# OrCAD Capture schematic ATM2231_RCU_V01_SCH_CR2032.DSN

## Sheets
1 1.TITLE: title: ATM2231_REMOTE_CONTROL_REF_DESIGN; rev: 01
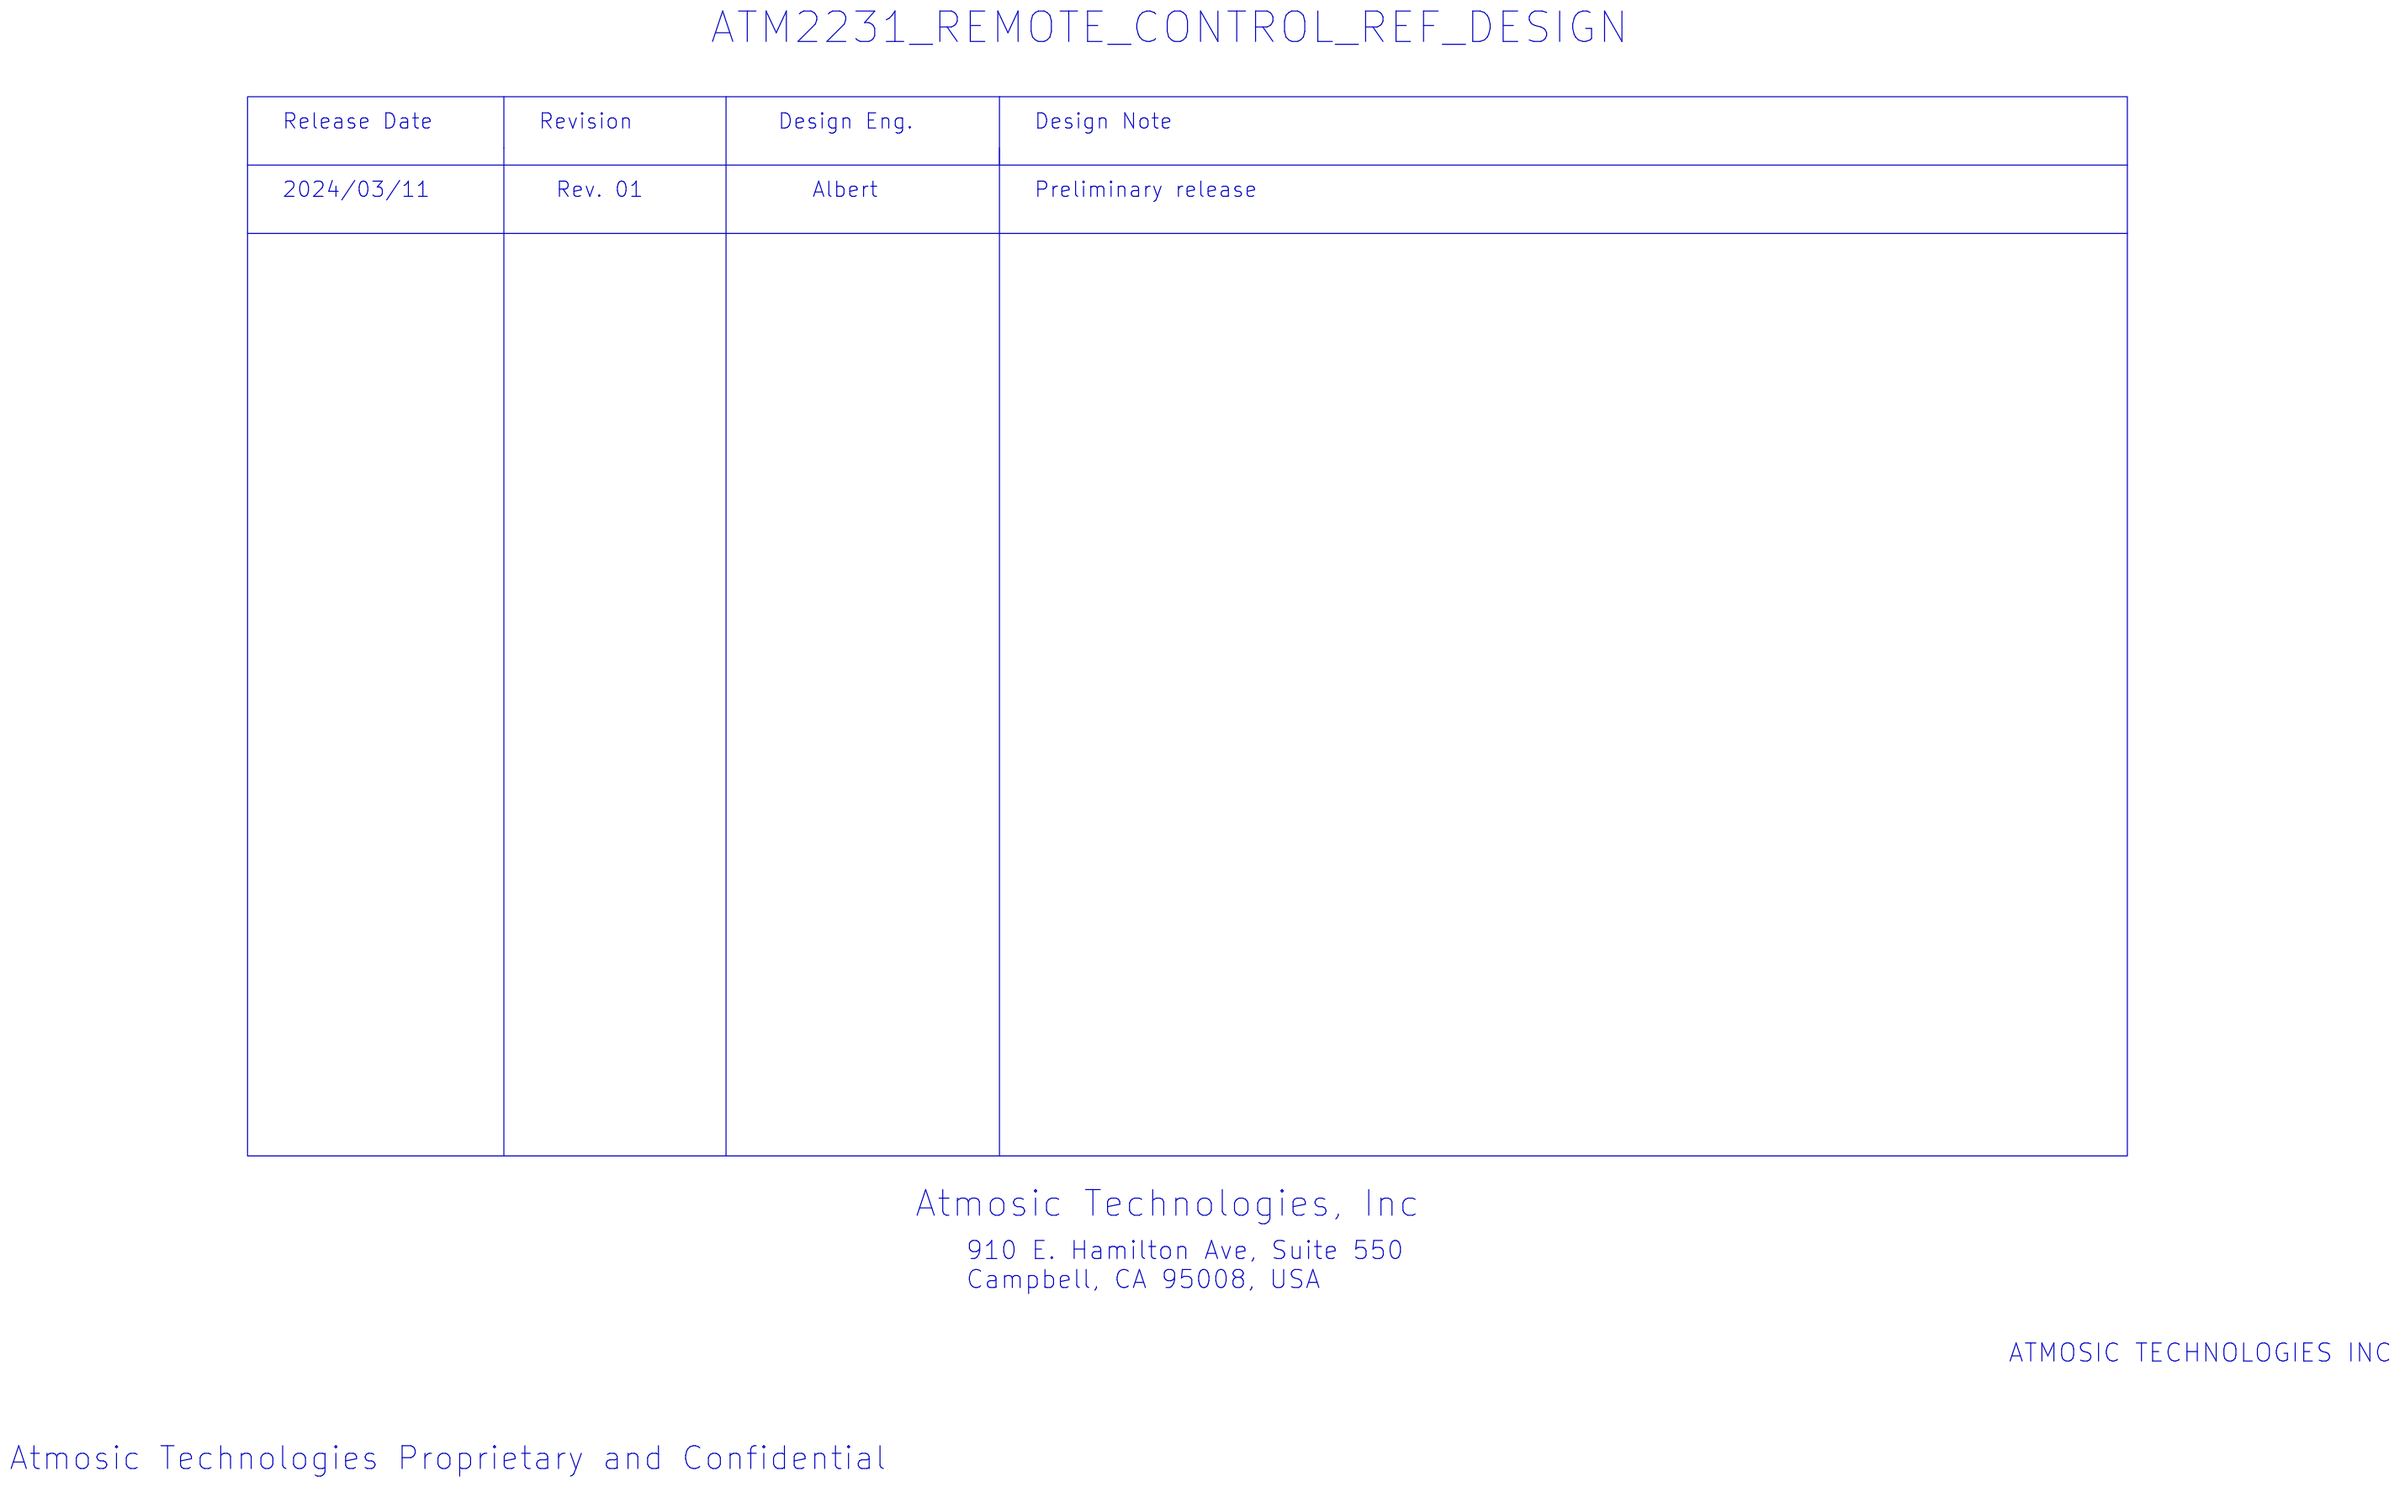
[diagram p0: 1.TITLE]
2 2.BLOCK DIAGRAM
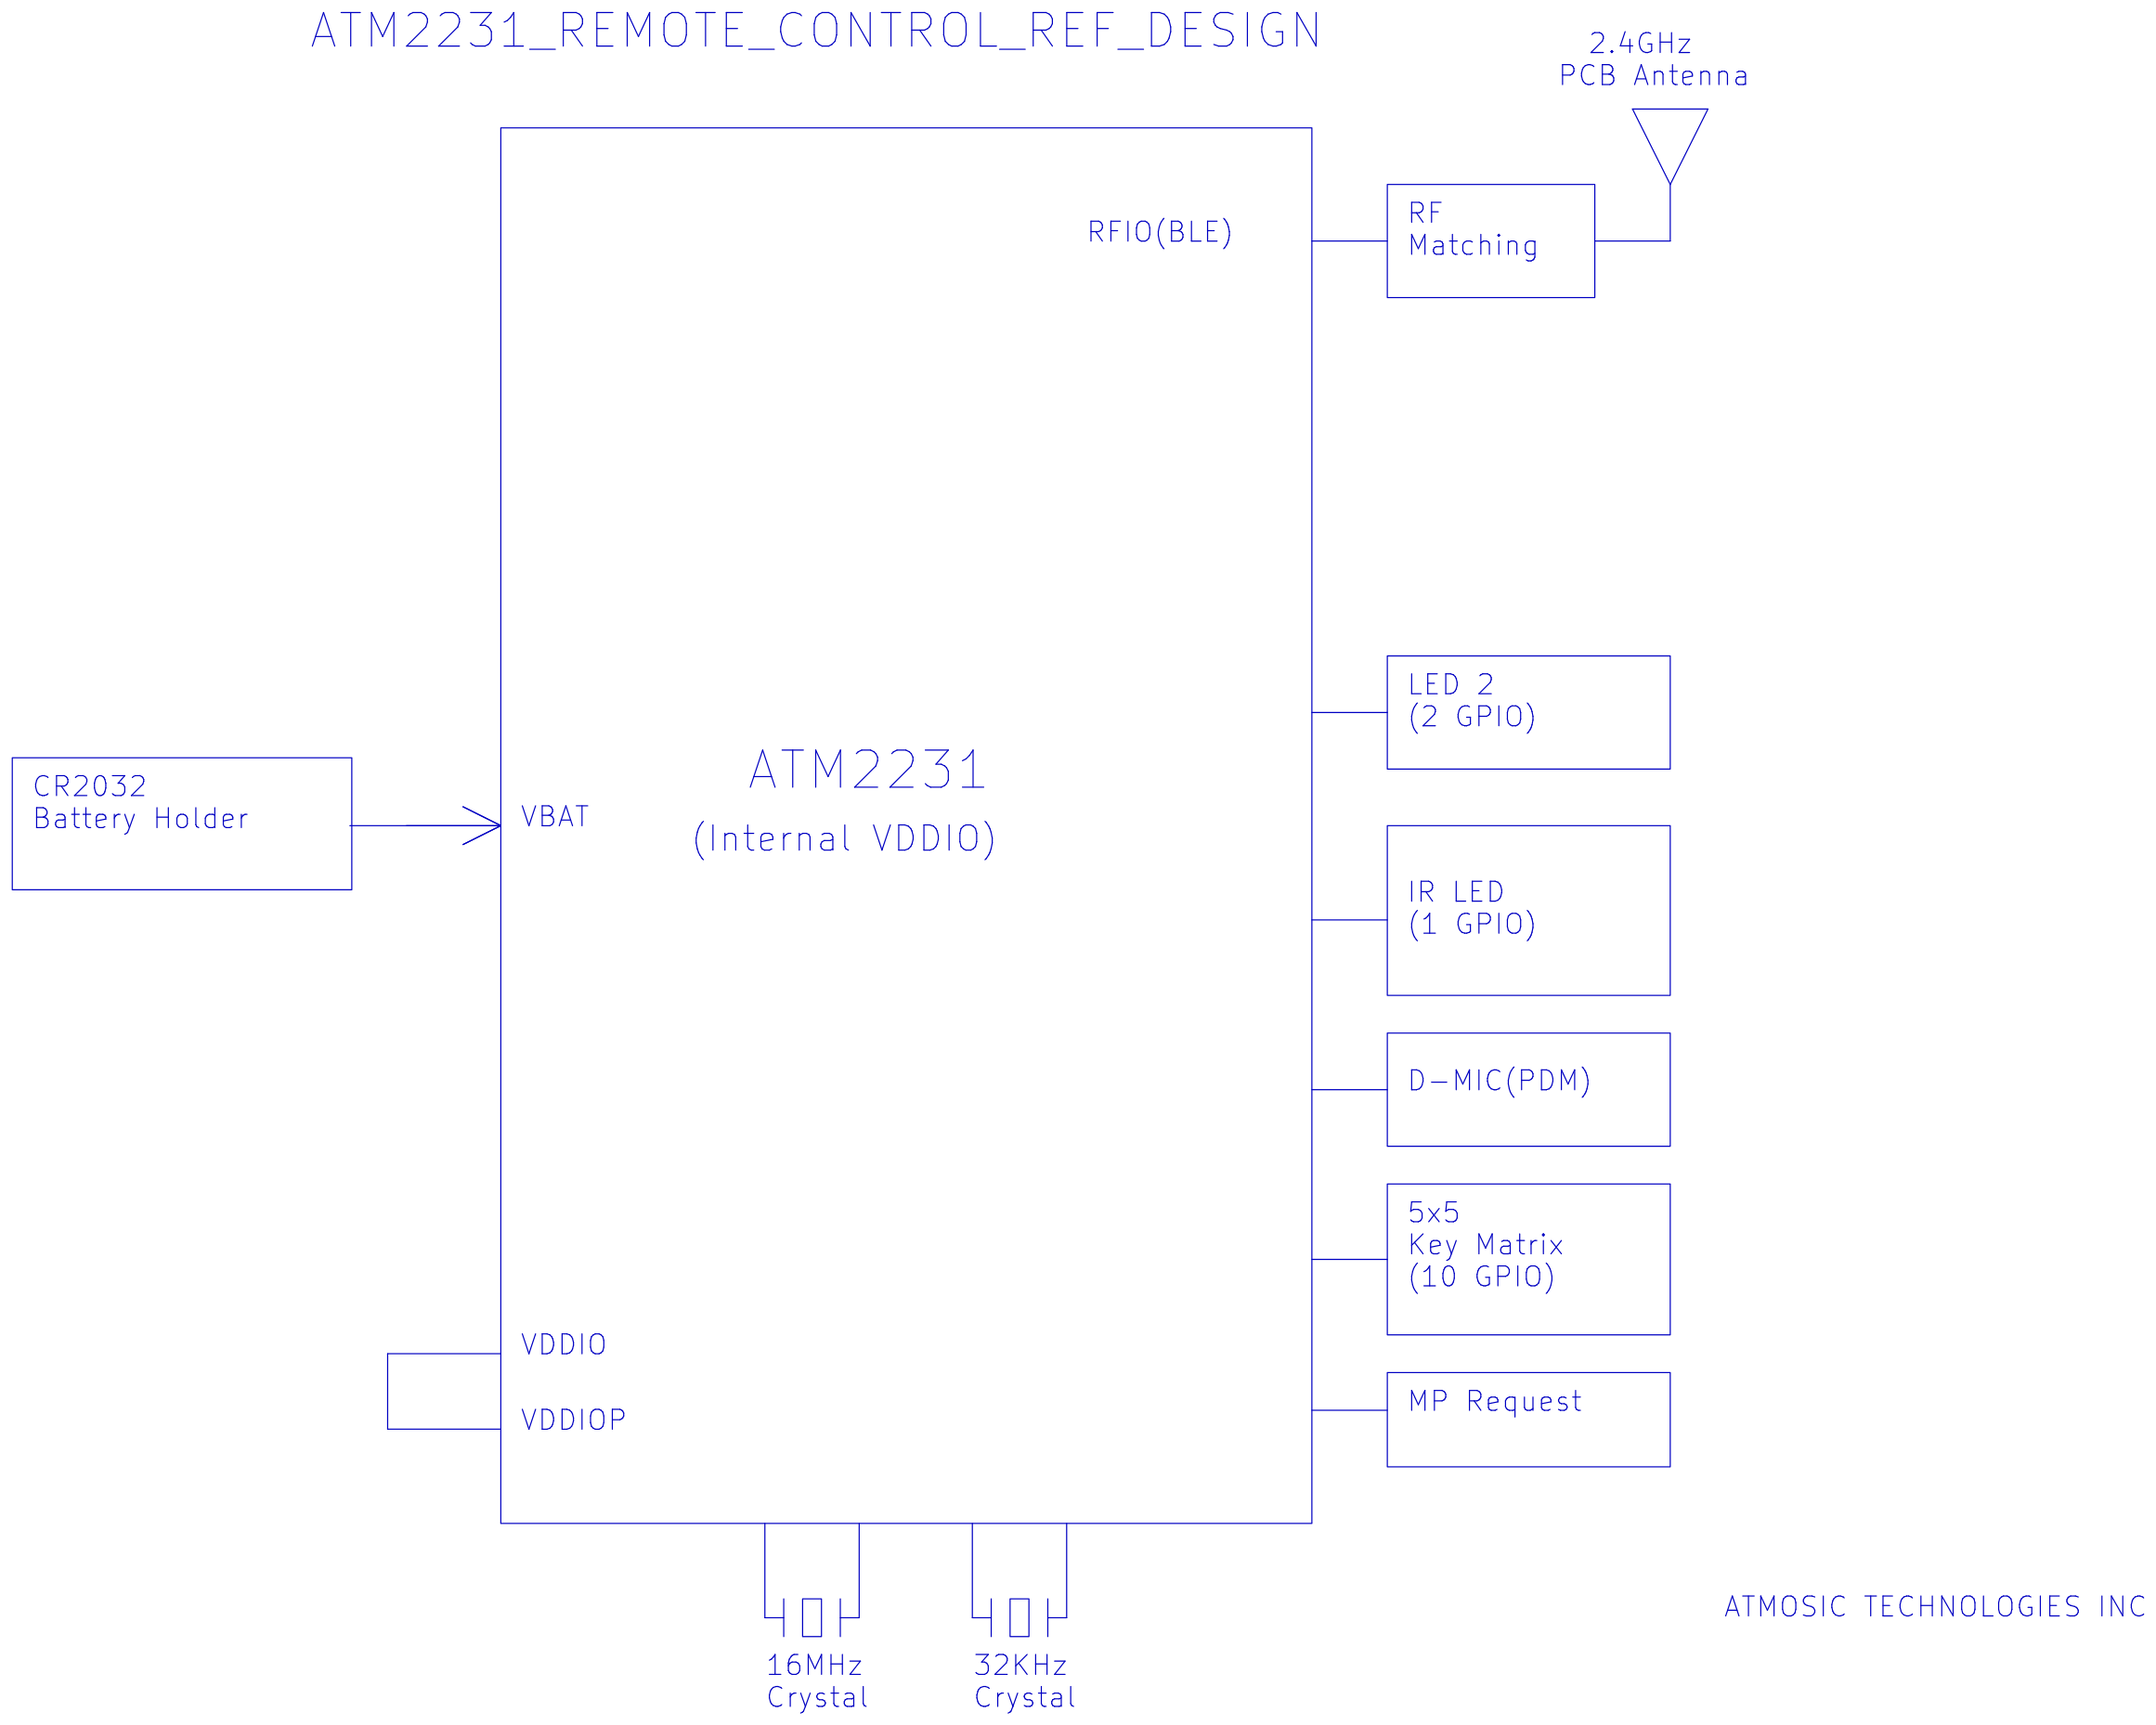
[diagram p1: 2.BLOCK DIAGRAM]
3 3.ATM2231: size C
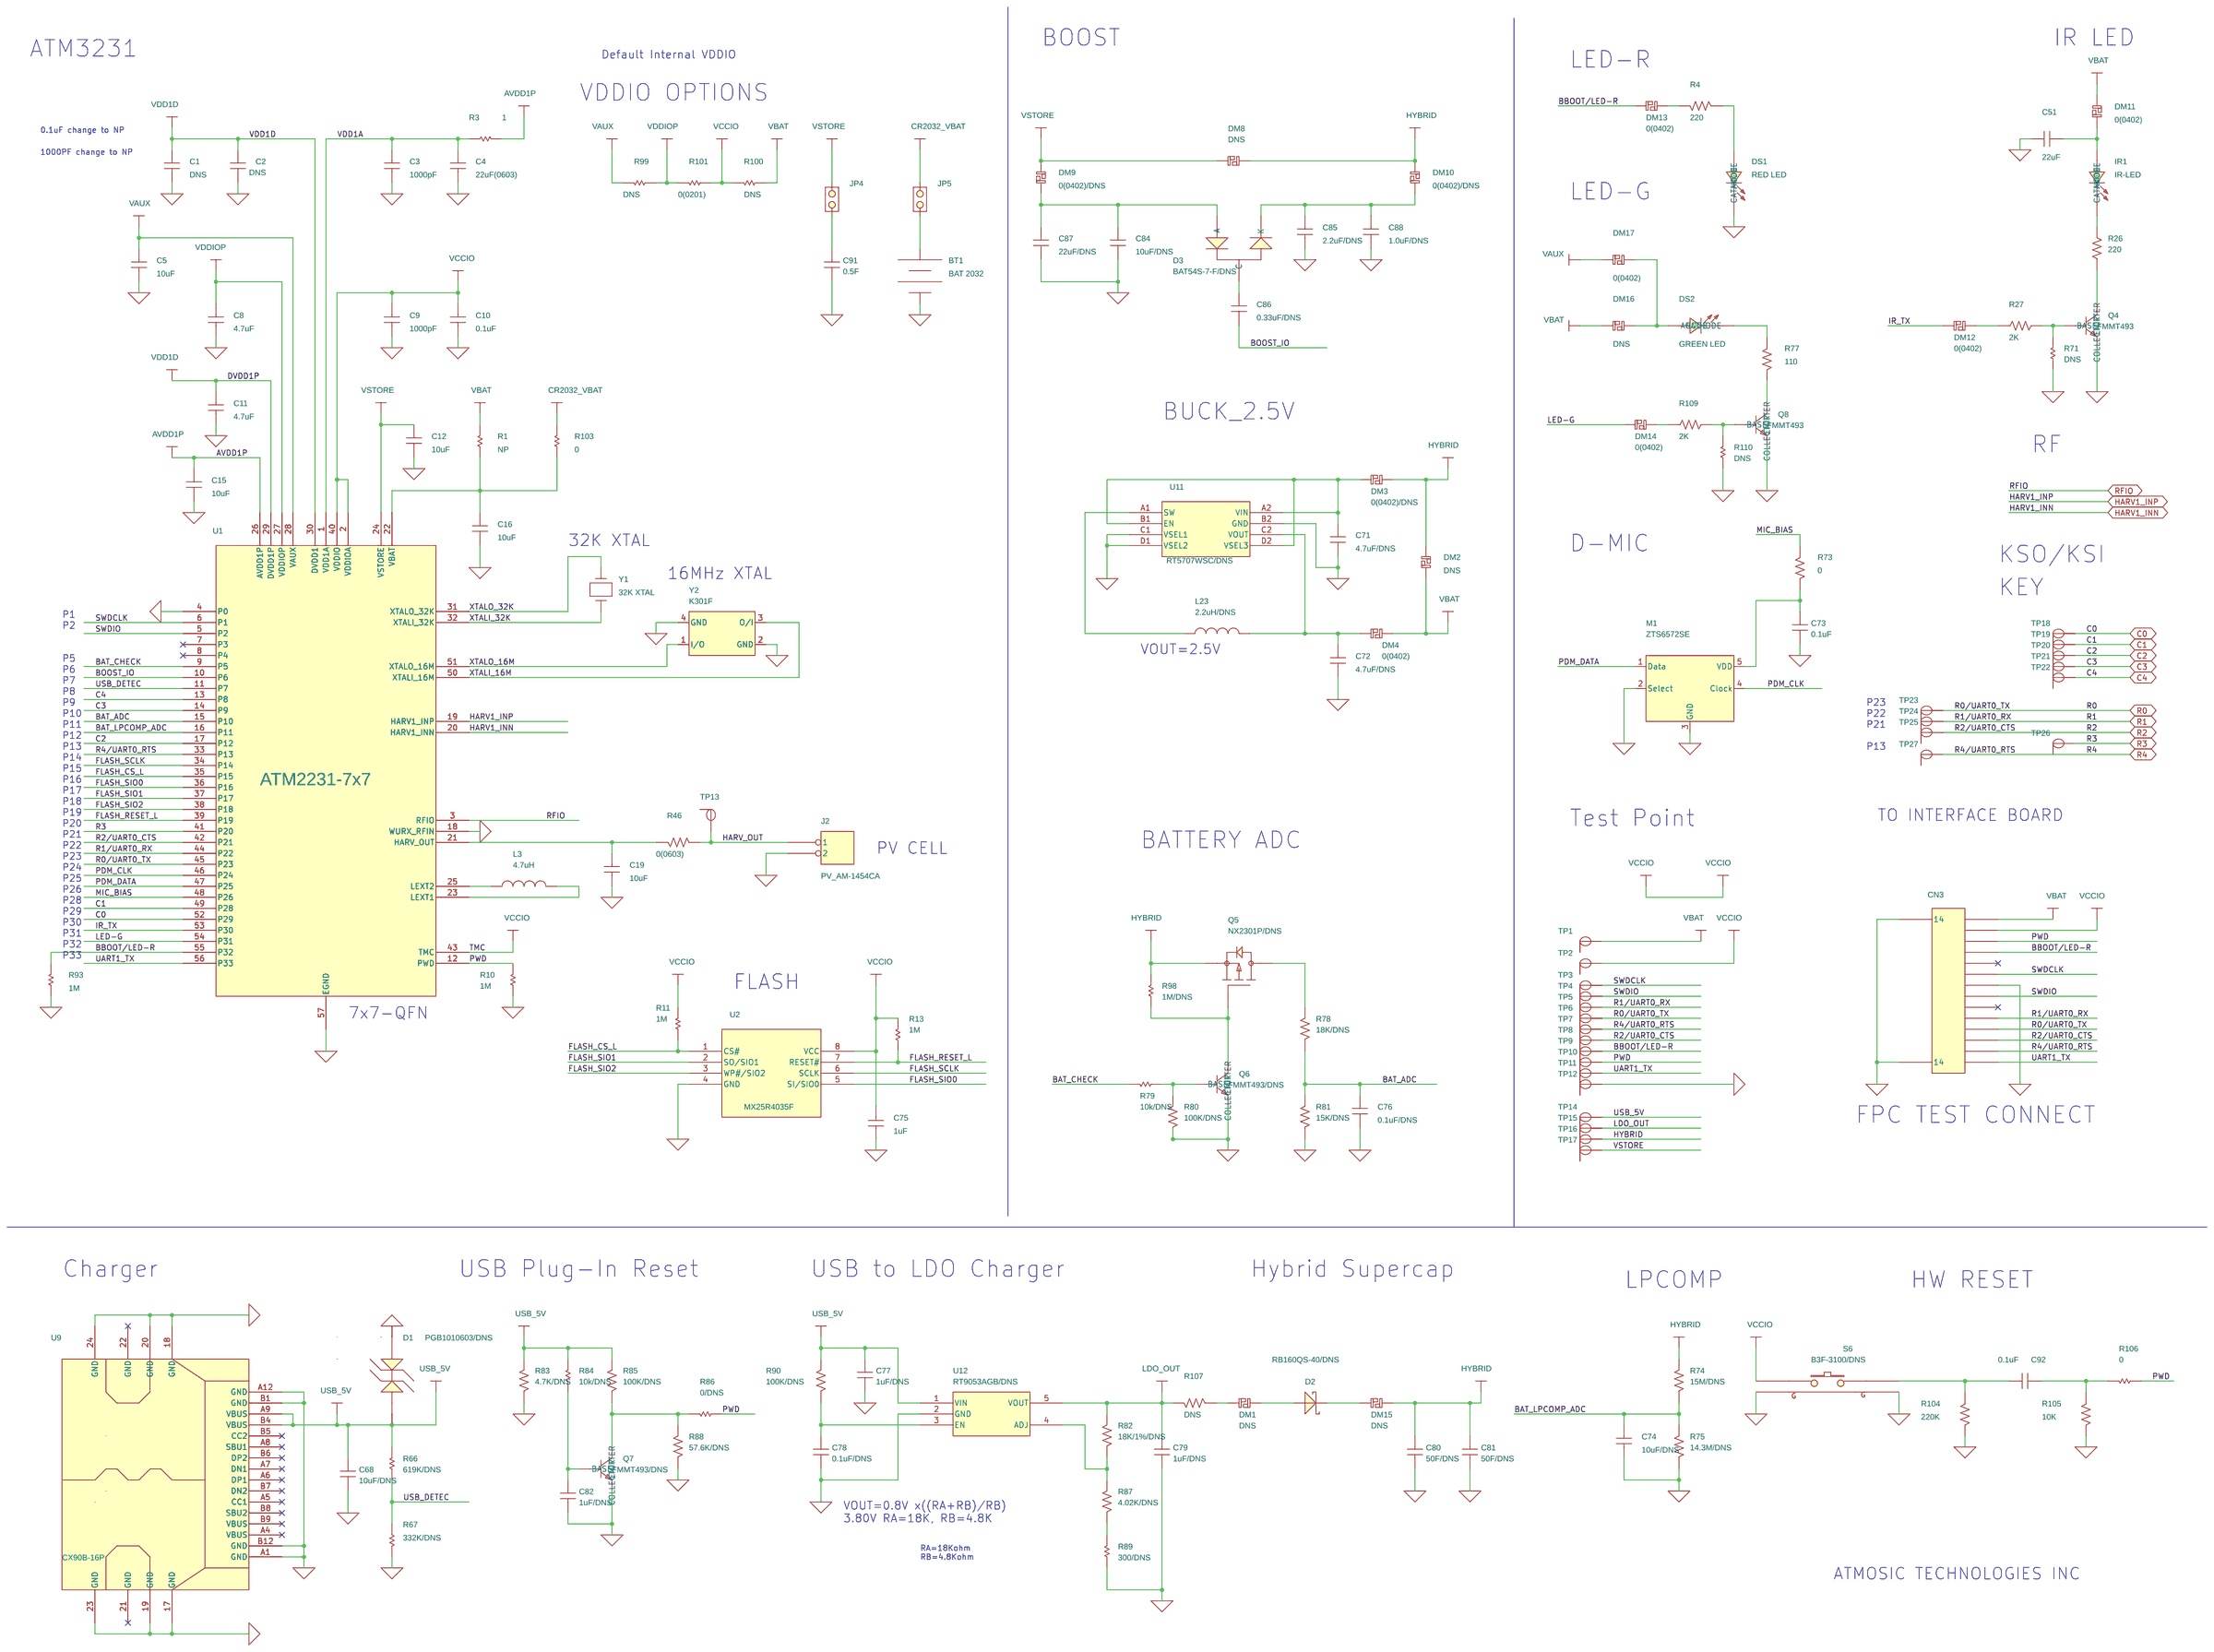
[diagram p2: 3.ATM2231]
4 4.KEY: size B
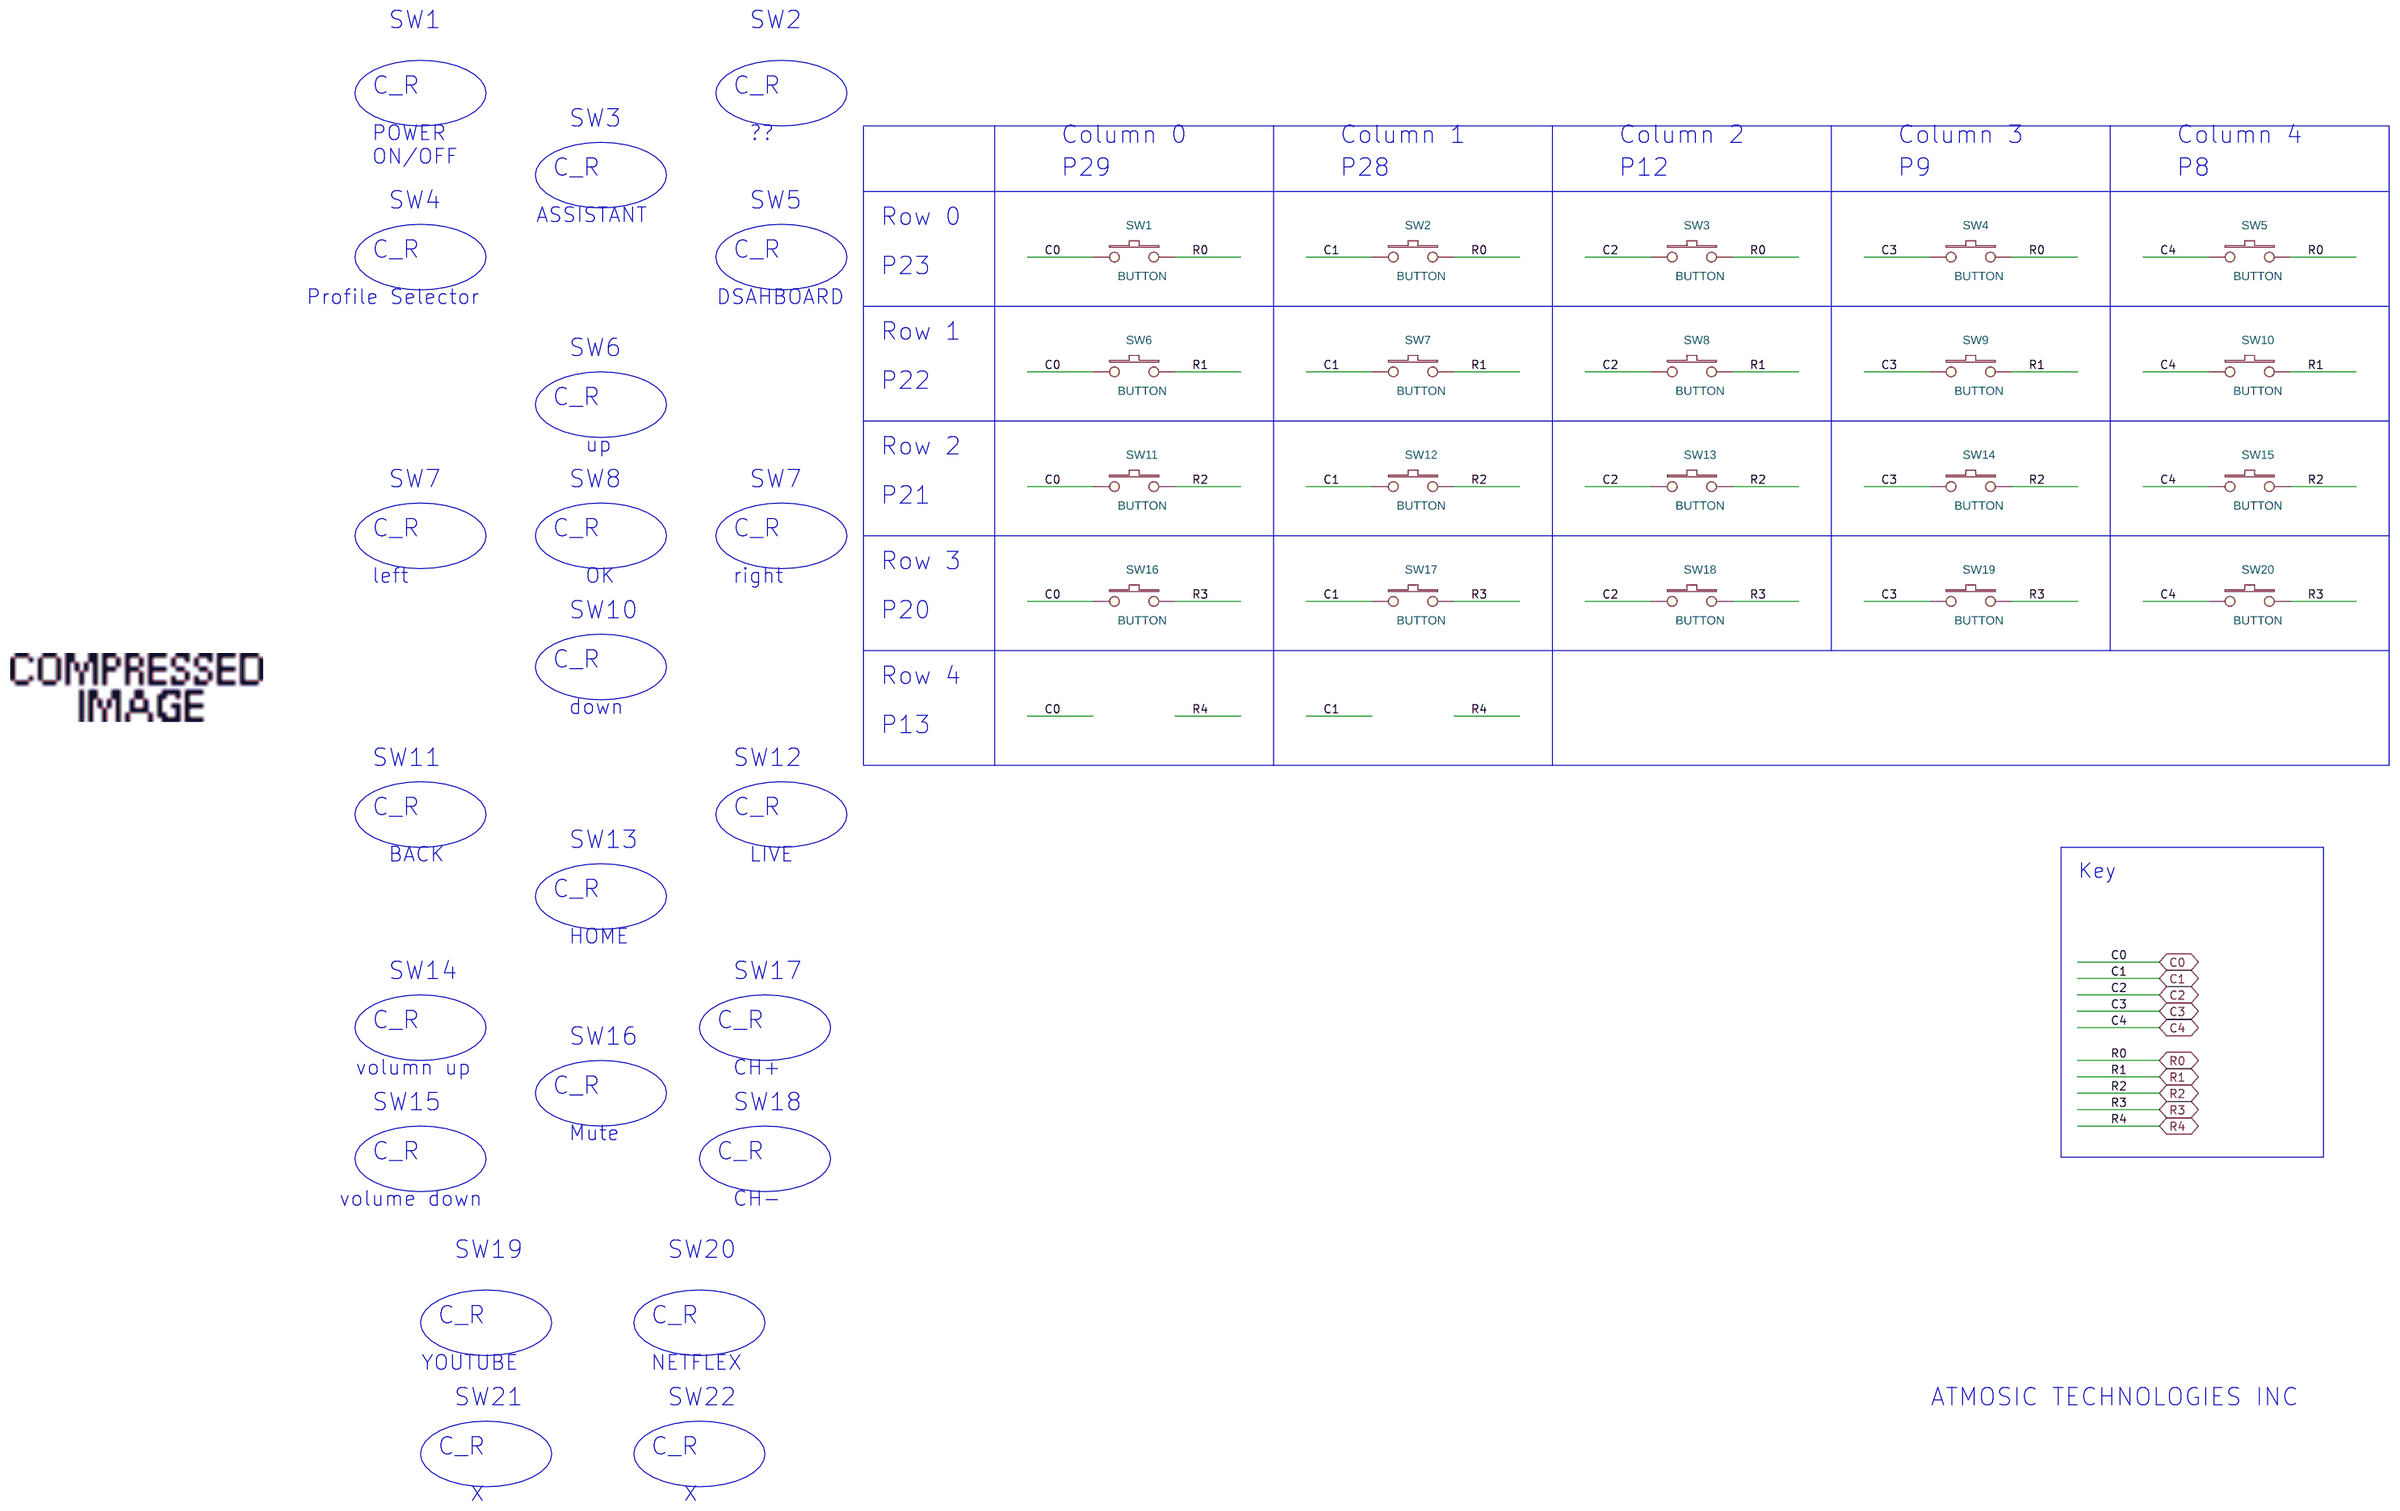
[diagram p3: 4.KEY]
5 5.RF: size A
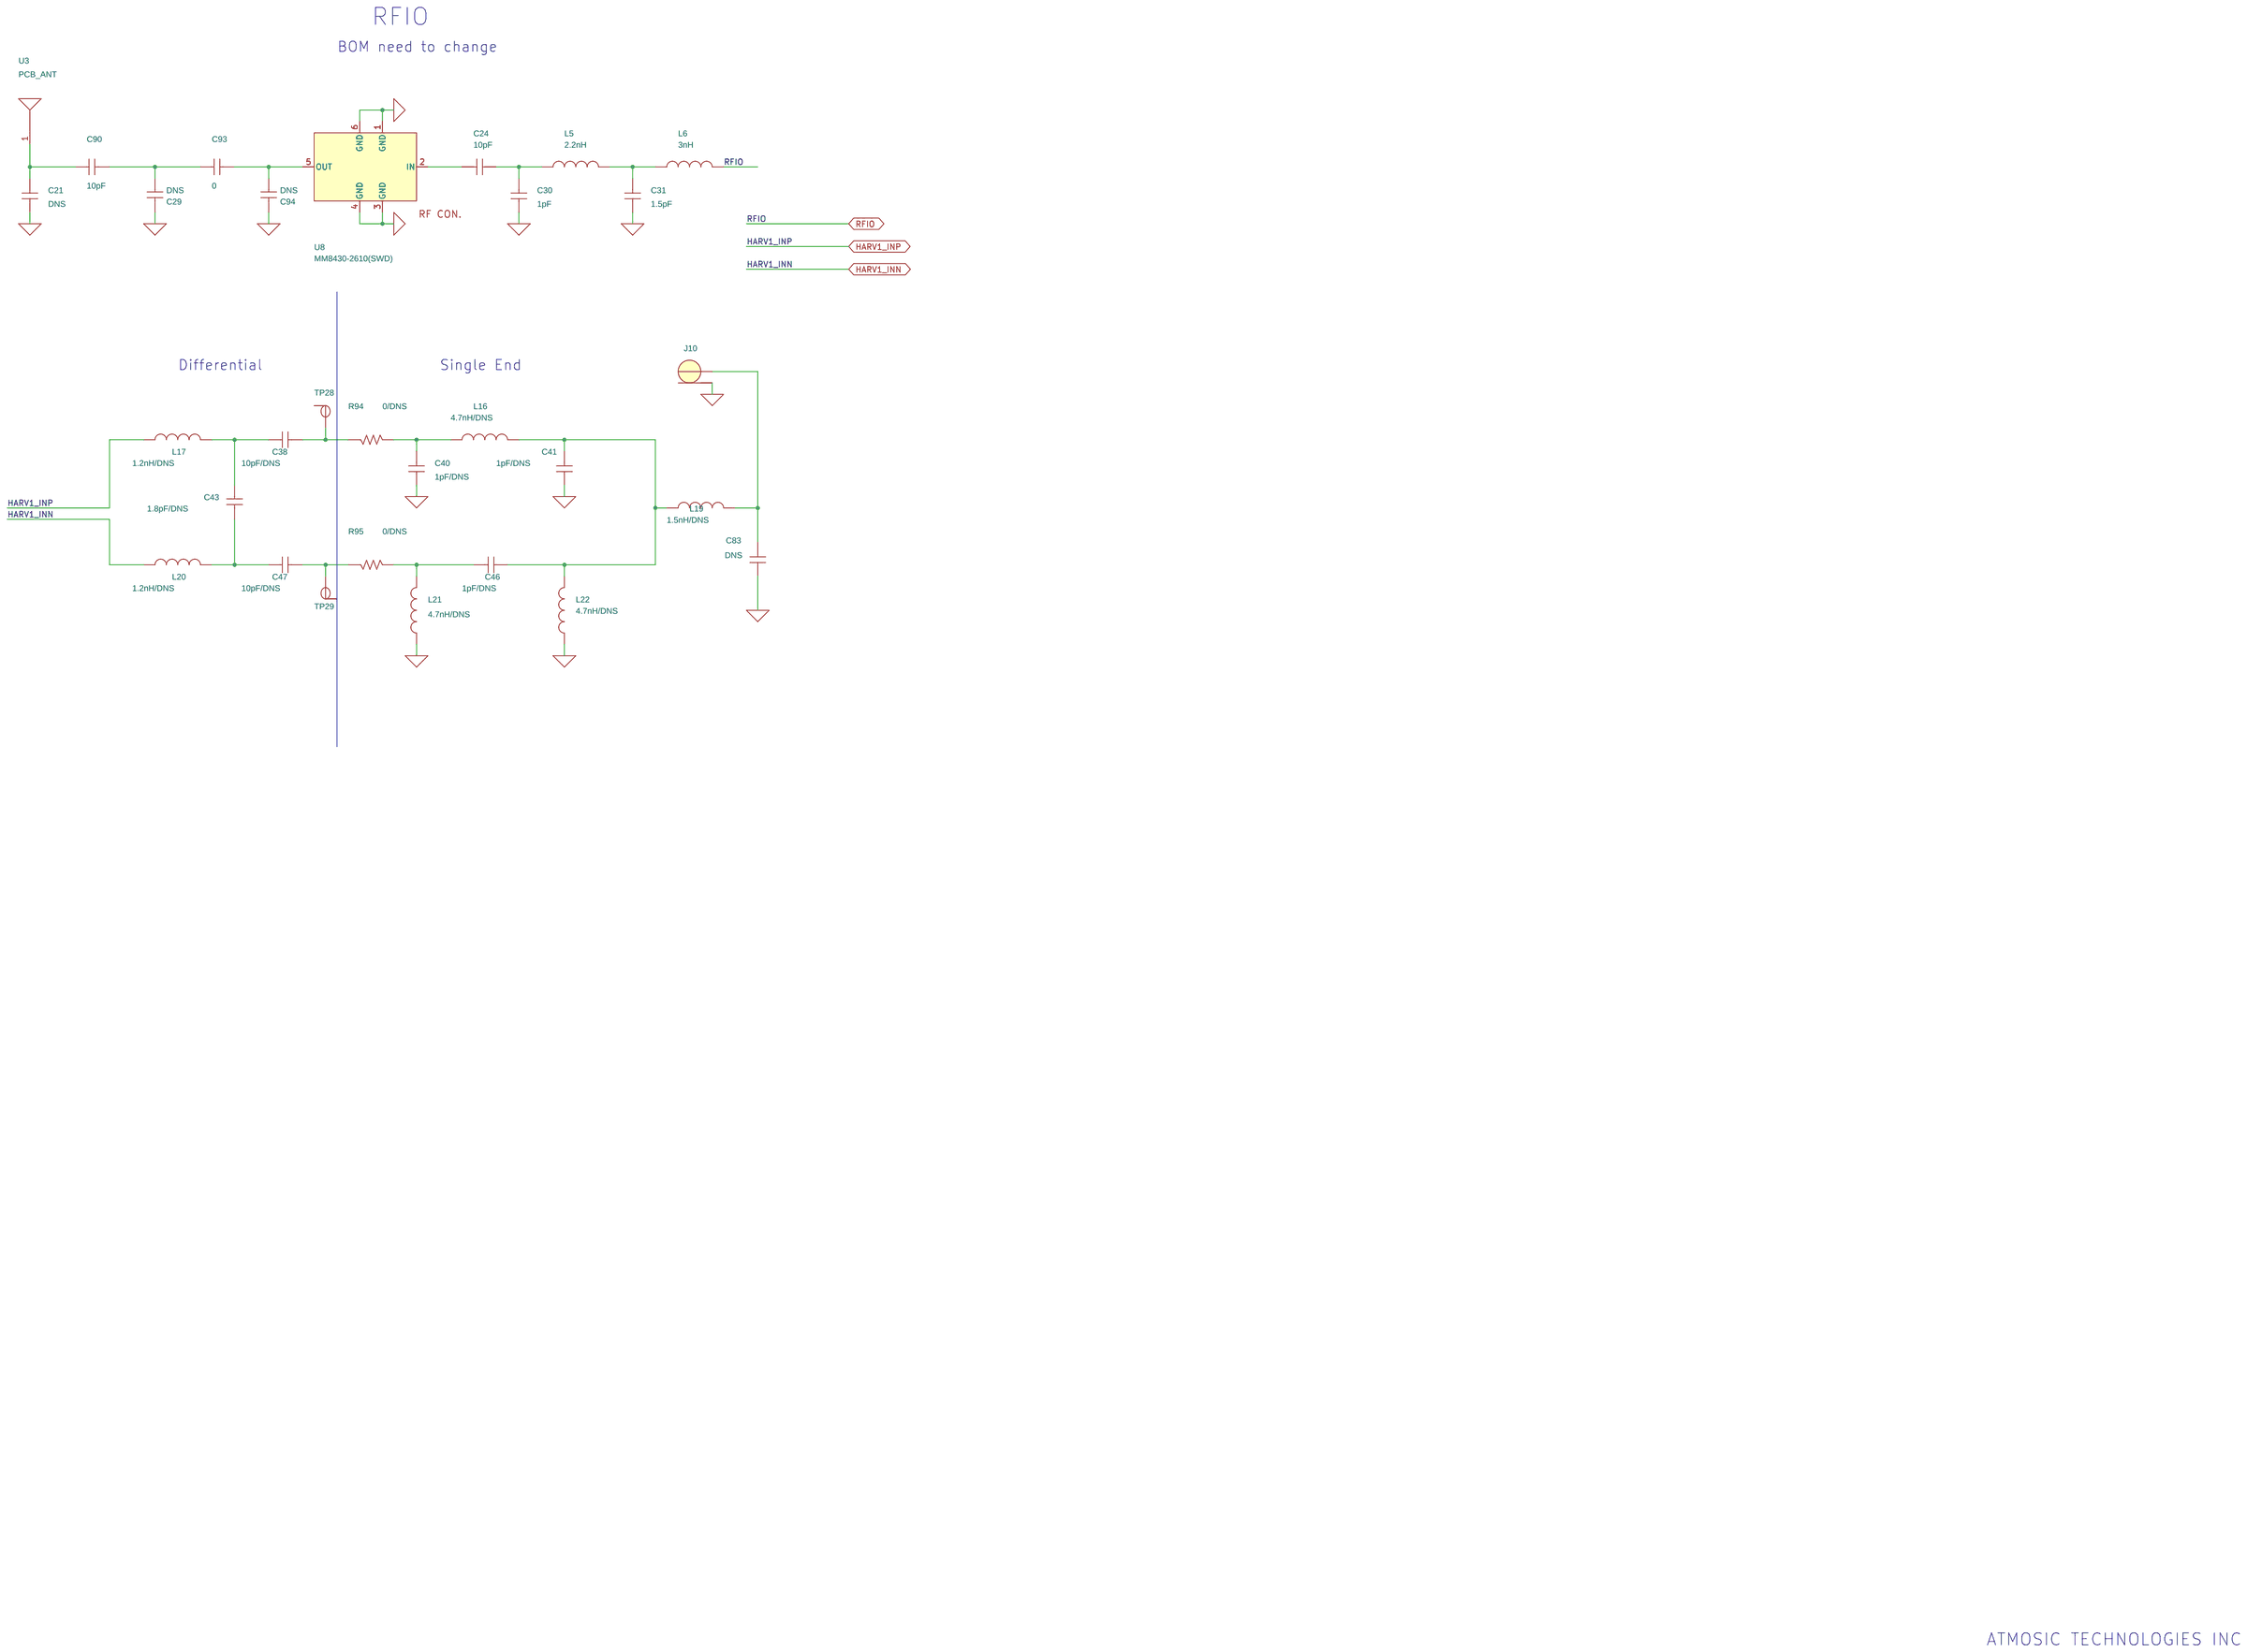
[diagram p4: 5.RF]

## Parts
sheet 3.ATM2231
BT1  BAT 2032  [SMTU2032_LF-2487805]
C1  DNS  [0402]
C2  DNS  [0402]
C3  1000pF  [0402]
C4  22uF(0603)  [0603]
C5  10uF  [0402]
C8  4.7uF  [0402]
C9  1000pF  [0402]
C10  0.1uF  [0402]
C11  4.7uF  [0402]
C12  10uF  [0402]
C15  10uF  [0402]
C16  10uF  [0402]
C19  10uF  [0402]
C51  22uF  [0603]
C68  10uF/DNS  [0402]
C71  4.7uF/DNS  [0402]
C72  4.7uF/DNS  [0402]
C73  0.1uF  [0402]
C74  10uF/DNS  [0402]
C75  1uF  [0402]
C76  0.1uF/DNS  [0402]
C77  1uF/DNS  [0402]
C78  0.1uF/DNS  [0402]
C79  1uF/DNS  [0402]
C80  50F/DNS  [C_VEL08253R8506G]
C81  50F/DNS  [C_VEL08253R8506G]
C82  1uF/DNS  [0402]
C84  10uF/DNS  [0603]
C85  2.2uF/DNS  [0402]
C86  0.33uF/DNS  [0603]
C87  22uF/DNS  [0603]
C88  1.0uF/DNS  [0402]
C91  0.5F  [IR_SMD]
C92  0.1uF  [0402]
CN3  05002HR-14CE  [FFC/0.5mm/14PIN]
D1  PGB1010603/DNS  [PGB1010603]
D2  RB160QS-40/DNS  [SMD1006]
D3  BAT54S-7-F/DNS  [SOT23]
DM1  DNS  [0402-DUMMY]
DM2  DNS  [0402-DUMMY]
DM3  0(0402)/DNS  [0402-DUMMY]
DM4  0(0402)  [0402-DUMMY]
DM8  DNS  [0402-DUMMY]
DM9  0(0402)/DNS  [0402-DUMMY]
DM10  0(0402)/DNS  [0402-DUMMY]
DM11  0(0402)  [0402-DUMMY]
DM12  0(0402)  [0402-DUMMY]
DM13  0(0402)  [0402-DUMMY]
DM14  0(0402)  [0402-DUMMY]
DM15  DNS  [0402-DUMMY]
DM16  DNS  [0402-DUMMY]
DM17  0(0402)  [0402-DUMMY]
DS1  RED LED  [LED-0402]
DS2  GREEN LED  [LED-0402]
IR1  IR-LED  [LED-L-524EIR1C]
J2  PV_AM-1454CA  [PV_CON]
JP4  JUMPER-2  [HDR1X2]
JP5  JUMPER-2  [HDR1X2]
L3  4.7uH  [IND-2016-2]
L23  2.2uH/DNS  [IND-2016-2]
M1  ZTS6572SE  [MIC\MEM\SPH0641LM4H-1]
Q4  FMMT493  [SOT23]
Q5  NX2301P/DNS  [SOT23]
Q6  FMMT493/DNS  [SOT23]
Q7  FMMT493/DNS  [SOT23]
Q8  FMMT493  [SOT23]
R1  NP  [0402]
R3  1  [0402]
R4  220  [0402]
R10  1M  [0402]
R11  1M  [0402]
R13  1M  [0402]
R26  220  [0402]
R27  2K  [0402]
R46  0(0603)  [0603]
R66  619K/DNS  [0402]
R67  332K/DNS  [0402]
R71  DNS  [0402]
R73  0  [0402]
R74  15M/DNS  [0402]
R75  14.3M/DNS  [0402]
R77  110  [0402]
R78  18K/DNS  [0402]
R79  10k/DNS  [0402]
R80  100K/DNS  [0402]
R81  15K/DNS  [0402]
R82  18K/1%/DNS  [0402]
R83  4.7K/DNS  [0402]
R84  10k/DNS  [0402]
R85  100K/DNS  [0402]
R86  0/DNS  [0402]
R87  4.02K/DNS  [0402]
R88  57.6K/DNS  [0402]
R89  300/DNS  [0402]
R90  100K/DNS  [0402]
R93  1M  [0402]
R98  1M/DNS  [0402]
R99  DNS  [0201]
R100  DNS  [0201]
R101  0(0201)  [0201]
R103  0  [0402]
R104  220K  [0402]
R105  10K  [0402]
R106  0  [0402]
R107  DNS  [1206]
R109  2K  [0402]
R110  DNS  [0402]
S6  B3F-3100/DNS  [SWI-SM-PTS645]
TP1  TP  [TP2]
TP2  TP  [TP2]
TP3  TP  [TP2]
TP4  TP  [TP2]
TP5  TP  [TP2]
TP6  TP  [TP2]
TP7  TP  [TP2]
TP8  TP  [TP2]
TP9  TP  [TP2]
TP10  TP  [TP2]
TP11  TP  [TP2]
TP12  TP  [TP2]
TP13  TP  [TP2]
TP14  TP  [TP2]
TP15  TP  [TP2]
TP16  TP  [TP2]
TP17  TP  [TP2]
TP18  TP  [TP2]
TP19  TP  [TP2]
TP20  TP  [TP2]
TP21  TP  [TP2]
TP22  TP  [TP2]
TP23  TP  [TP2]
TP24  TP  [TP2]
TP25  TP  [TP2]
TP26  TP  [TP2]
TP27  TP  [TP2]
U1  ATM2231-7x7  [QFN-56-7X7-0.4MM-EP5.2MM]
U2  MX25R4035F  [SO8NB]
U9  CX90B-16P  [CX90B-16P-1]
U11  RT5707WSC/DNS  [8B_WL_CSP]
U12  RT9053AGB/DNS  [SOT23-5]
Y1  32K XTAL  [XTAL-SMD2-2.0X1.2MM]
Y2  K301F  [XTAL-ECX-2236]
sheet 4.KEY
SW1  BUTTON  [RC3_A]
SW2  BUTTON  [RC3_A]
SW3  BUTTON  [RC3_A]
SW4  BUTTON  [RC3_A]
SW5  BUTTON  [RC3_A]
SW6  BUTTON  [RC3_A]
SW7  BUTTON  [RC3_A]
SW8  BUTTON  [RC3_A]
SW9  BUTTON  [RC3_A]
SW10  BUTTON  [RC3_A]
SW11  BUTTON  [RC3_A]
SW12  BUTTON  [RC3_A]
SW13  BUTTON  [RC3_A]
SW14  BUTTON  [RC3_A]
SW15  BUTTON  [RC3_A]
SW16  BUTTON  [RC3_A]
SW17  BUTTON  [RC3_A]
SW18  BUTTON  [RC3_A]
SW19  BUTTON  [RC3_A]
SW20  BUTTON  [RC3_A]
sheet 5.RF
C21  DNS  [0402]
C24  10pF  [0402]
C29  DNS  [0402]
C30  1pF  [0402]
C31  1.5pF  [0402]
C38  10pF/DNS  [0402]
C40  1pF/DNS  [0402]
C41  1pF/DNS  [0402]
C43  1.8pF/DNS  [0402]
C46  1pF/DNS  [0402]
C47  10pF/DNS  [0402]
C83  DNS  [0402]
C90  10pF  [0402]
C93  0  [0402]
C94  DNS  [0402]
J10  CON RF 3PIN  [CON-HRS-UFL]
L5  2.2nH  [0402]
L6  3nH  [0402]
L16  4.7nH/DNS  [0402]
L17  1.2nH/DNS  [0402]
L19  1.5nH/DNS  [0402]
L20  1.2nH/DNS  [0402]
L21  4.7nH/DNS  [0402]
L22  4.7nH/DNS  [0402]
R94  0/DNS  [0402]
R95  0/DNS  [0402]
TP28  TP  [HARV_TP2]
TP29  TP  [HARV_TP2]
U3  PCB_ANT  [ANTENNA_IIFA_4A]
U8  MM8430-2610(SWD)  [RF_SWD]

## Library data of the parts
BT1 = BAT
C1 C2 C21 C29 C83 C94 = SMALL_CAP
C3 C9 = SMALL_CAP: Part Number: GRT1555C1H102JA02D; Vendor: MURATA
C4 C51 = SMALL_CAP: Part Number: CC0603MRX5R5BB226; Vendor: MURATA
C5 C12 C15 C16 C19 C68 C74 = SMALL_CAP: Part Number: GRM155R60J106ME15D; Vendor: MURATA
C8 C11 C71 = SMALL_CAP: Part Number: GRM155R60J475ME47D; Vendor: MURATA
C10 C73 C76 C78 C92 = SMALL_CAP: Part Number: GRM1555R71H104KE14; Vendor: MURATA
C72 = SMALL_CAP: Part Number: 0402X475M100CT; Vendor: MURATA
C75 C77 C79 C82 = SMALL_CAP: Part Number: GRM1555R71H105KE14; Vendor: MURATA
C80 C81 = SMALL_CAP: Part Number: HS/HSL 1016-3R8306-R; Vendor: EATON
C84 = SMALL_CAP: Part Number: GRM188R61E106MA73D; Vendor: MURATA
C85 = SMALL_CAP: Part Number: 0402X225M100CT; Vendor: MURATA
C86 = SMALL_CAP: Part Number: 0402X334K100CT; Vendor: MURATA
C87 = SMALL_CAP: Part Number: GRM188C80J226ME15D; Vendor: MURATA
C88 = SMALL_CAP: Part Number: 0402X105M250CT; Vendor: MURATA
C91 = SMALL_CAP: Part Number: HP-3R0-J504VY; Vendor: EATON
CN3 = FFC_14PIN_0.5MM_D: Part Number: 503480-1400; Vendor: MOLEX
D1 = ESDP: Vendor: LITTELFUSE
D2 = TMP_145458: Part Number: RB160QS-40; Vendor: ROHM
D3 = DIODE_1A2C3COM: Part Number: BAT54CT-7-F; Vendor: DIODES
DM1 DM3 DM4 DM9-DM17 = DUMMY: Part Number: WR04X000PTL; Vendor: WALSIN
DM2 DM8 = DUMMY
DS1 = LED: Part Number: XZMER68W-3; Vendor: SUNLED
DS2 = LED: Part Number: XZVGR68W-3; Vendor: SUNLED
IR1 = LED: Part Number: BIR-BM13E4G-2.; Vendor: YELLOW STONE CORP.
J2 = HEADER_2: Part Number: AM-1454CA; Vendor: PANASONIC - BSG
JP4 JP5 = JUMPER-2: MF: Amphenol ICC (FCI); Part Number: M20-9750342
L3 = INDUCTOR: Part Number: LQM2MPN4R7MG0L; Vendor: MURATA
L23 = INDUCTOR: Part Number: VLS201610CX-2R2M; Vendor: TDK
M1 = MP34DT01-M_0: Vendor: ZILLTEK
Q4 Q8 = MMBT3904(NPN-SOT-346): Vendor: DIODES
Q5 = PWRMOSFET_EP_GSD_0: Part Number: NX2301P,215; Vendor: Nexperia USA Inc
Q6 Q7 = MMBT3904(NPN-SOT-346): Part Number: FMMT493; Vendor: DIODES
R1 R99-R101 = SMALL_R1: Vendor: WALSIN
R3 = SMALL_R1: Part Number: RC0402FR-071RL; Vendor: YAGEO
R4 R26 = R_0: Part Number: WR04X2200FTL; Vendor: WALSIN
R10 R11 R13 R93 R98 = SMALL_R1: Part Number: WR04X1004FTL; Vendor: WALSIN
R27 R109 = R_0: Part Number: WR04X2001FTL; Vendor: WALSIN
R46 = R_0: Part Number: WR06X000 PTL; Vendor: WALSIN
R66 = SMALL_R1: Part Number: CR-02FL6-619K; Vendor: VIKING
R67 = SMALL_R1: Part Number: CR-02FL6-332K; Vendor: VIKING
R71 R110 = SMALL_R1
R73 R94 R95 = R_0: Part Number: WR04X000PTL; Vendor: WALSIN
R74 = R_0: Part Number: 0402WGF1505TCE; Vendor: YAGEO
R75 = R_0: Part Number: 0402WGF1435TCE; Vendor: YAGEO
R77 = R_0: Part Number: WR04X1100FTL; Vendor: WALSIN
R78 R83 = R_0: Part Number: RC0402JR-0718ML; Vendor: YAGEO
R79 R84 = SMALL_R1: Part Number: WR04X1002FTL; Vendor: WALSIN
R80 R85 R90 = R_0: Part Number: WR04X1003FTL; Vendor: WALSIN
R81 = R_0: Part Number: RC0402JR-0715ML; Vendor: YAGEO
R82 = R_0: Part Number: WR04X1802FTL; Vendor: WALSIN
R86 R103 R106 = SMALL_R1: Part Number: WR04X000PTL; Vendor: WALSIN
R87 = R_0: Part Number: WR04X4021FTL; Vendor: WALSIN
R88 = R_0: Part Number: AC0402FR-0757K6L; Vendor: YAGEO
R89 = SMALL_R1: Part Number: WR04X301JTL; Vendor: WALSIN
R104 = R_0: Part Number: WR04X224JTL; Vendor: WALSIN
R105 = R_0: Part Number: RC0402JR-0710KL; Vendor: WALSIN
R107 = R_0: Part Number: CR1206-J/-3R0ELF; Vendor: Bourns Inc.
S6 = SW-TACT-4P-5_0: MF: OMRON; Part Number: B3F-3100; Vendor: OMRON
TP1-TP29 = TP_0
U1 = SYDNEY-7X7_1: Part Number: ATM3231; Vendor: ATMOSIC
U2 = LM258DRG3_0: Part Number: MX25R4035FM1IH1; Vendor: MACRONIX
U9 = USB_Connector_TypeC_5: Vendor: HIROSE
U11 = BUCK_RT5707AWSC: Part Number: RT5707WSC; Vendor: RICHTEK
U12 = LDO_RT9179PB: Part Number: RT9053AGB; Vendor: RICHTEK
Y1 = XTAL_0: Part Number: ECS-.327-7-12R-TR; Vendor: ECS
Y2 = XTAL-OSC-4P_3: Part Number: ECS-160-8-36-JTN-TR; Vendor: ECS
SW1-SW20 = SW_PUSHBUTTON_0
C24 C38 C47 C90 = SMALL_CAP: Part Number: 500R07S100JV4T; Vendor: JOHANSON
C30 C40 C41 C46 = SMALL_CAP: Part Number: 500R07S1R0BV4T; Vendor: JOHANSON
C31 = SMALL_CAP: Part Number: GRM1555C1H1R5BA01D; Vendor: MURATA
C43 = SMALL_CAP: Part Number: 500R07S1R8BV4T; Vendor: JOHANSON
C93 = SMALL_CAP: Part Number: WR04X000PTL; Vendor: WALSIN
J10 = CON_RF_3PIN
L5 = INDUCTOR: Part Number: LQG15HS2N2S02D; Vendor: MURATA
L6 = INDUCTOR: Part Number: LQG15HS3N0S02D; Vendor: MURATA
L16 L21 L22 = INDUCTOR: Part Number: MHQ1005P4N7BT000; Vendor: TDK
L17 L20 = INDUCTOR: Part Number: MHQ1005P1N2BT000; Vendor: TDK
L19 = INDUCTOR: Part Number: MHQ1005P1N5BT000; Vendor: TDK
U3 = PCB_ANT_3
U8 = RF_SWJ_7: Part Number: MM8430-2610; Vendor: MURATA

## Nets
AVDD1P: C15.1 R3.2 U1.26(AVDD1P)
DVDD1P: C1.1 C2.1 C11.1 U1.29(DVDD1P) U1.30(DVDD1)
GND_SIGNAL: BT1.2(NEG) C1.2 C2.2 C3.2 C4.2 C5.2 C8.2 C9.2 C10.2 C11.2 C12.2 C15.2 C16.2 C19.2 C21.1 C29.2 C30.1 C31.1 C40.1 C41.1 C51.1 C68.2 C71.2 C72.2 C73.2 C74.2 C75.1 C76.2 C77.2 C78.2 C79.2 C80.2 C81.2 C82.2 C83.1 C84.2 C85.2 C87.2 C88.2 C91.2 C94.2 CN3.7 CN3.15(14) CN3.16(14) D1.2 DS1.1(CATHODE) J2.2 J10.2 J10.3 L21.1 L22.1 M1.2(Select) M1.3(GND) Q4.2(EMITTER) Q6.2(EMITTER) Q7.2(EMITTER) Q8.2(EMITTER) R10.1 R67.1 R71.1 R75.1 R80.1 R81.1 R83.1 R88.1 R89.1 R93.1 R104.2 R105.2 R110.1 S6.3 S6.4 TP12.1(TP) U1.4(P0) U1.18(WURX_RFIN) U1.57(EGND) U2.4(GND) U8.1(GND) U8.3(GND) U8.4(GND) U8.6(GND) U9.17(GND) U9.18(GND) U9.19(GND) U9.20(GND) U9.23(GND) U9.24(GND) U9.A1(GND) U9.A12(GND) U9.B1(GND) U9.B12(GND) U11.B2(GND) U11.C1(VSEL1) U11.D1(VSEL2) U12.2(GND) Y2.2(GND) Y2.4(GND)
VBAT: CN3.1 DM2.2 DM4.2 DM11.1 DM16.1 R1.2 R100.1 TP1.1(TP)
VCCIO: C9.1 C10.1 C75.2 CN3.2 R11.1 R13.1 R100.2 R101.1 S6.2 TP2.1(TP) U1.2(VDDIOA) U1.40(VDDIO) U1.43(TMC) U2.8(VCC)
VDD1A: C3.1 C4.1 R3.1 U1.1(VDD1A)
VDDIOP: C8.1 R99.1 R101.2 U1.27(VDDIOP)
BAT_ADC: C76.1 R78.1 R81.2 U1.15(P10)
BAT_CHECK: R79.1 U1.9(P5)
BAT_LPCOMP_ADC: C74.1 R74.1 R75.2 U1.16(P11)
BBOOT/LED-R: CN3.4 DM13.1 R93.2 TP9.1(TP) U1.55(P32)
BOOST_IO: C86.2 U1.10(P6)
C0: SW1.1 SW6.1 SW11.1 SW16.1 TP18.1(TP) U1.52(P29)
C1: SW2.1 SW7.1 SW12.1 SW17.1 TP19.1(TP) U1.49(P28)
C2: SW3.1 SW8.1 SW13.1 SW18.1 TP20.1(TP) U1.17(P12)
C3: SW4.1 SW9.1 SW14.1 SW19.1 TP21.1(TP) U1.14(P9)
C4: SW5.1 SW10.1 SW15.1 SW20.1 TP22.1(TP) U1.13(P8)
CR2032_VBAT: JP5.1 R103.2
FLASH_CS_L: R11.2 U1.35(P15) U2.1(CS#)
FLASH_RESET_L: R13.2 U1.39(P19) U2.7(RESET#)
FLASH_SCLK: U1.34(P14) U2.6(SCLK)
FLASH_SIO0: U1.36(P16) U2.5(SI/SIO0)
FLASH_SIO1: U1.37(P17) U2.2(SO/SIO1)
FLASH_SIO2: U1.38(P18) U2.3(WP#/SIO2)
HARV1_INN: L20.2 U1.20(HARV1_INN)
HARV1_INP: L17.2 U1.19(HARV1_INP)
HARV_OUT: J2.1 R46.2 TP13.1(TP)
HYBRID: C80.1 C81.1 DM2.1 DM3.2 DM8.2 DM10.1 DM15.2 Q5.2(SOURCE) R74.2 R98.1 TP16.1(TP)
IR_TX: DM12.1 U1.53(P30)
LDO_OUT: C79.1 R82.2 R107.2 TP15.1(TP) U12.5(VOUT)
LED-G: DM14.1 U1.54(P31)
MIC_BIAS: R73.1 U1.48(P26)
PDM_CLK: M1.4(Clock) U1.46(P24)
PDM_DATA: M1.1(Data) U1.47(P25)
PWD: CN3.3 R10.2 R86.1 R106.1 TP10.1(TP) U1.12(PWD)
R0: CN3.11 SW1.2 SW2.2 SW3.2 SW4.2 SW5.2 TP6.1(TP) TP23.1(TP) U1.45(P23)
R1: CN3.10 SW6.2 SW7.2 SW8.2 SW9.2 SW10.2 TP5.1(TP) TP24.1(TP) U1.44(P22)
R2: CN3.12 SW11.2 SW12.2 SW13.2 SW14.2 SW15.2 TP8.1(TP) TP25.1(TP) U1.42(P21)
R3: SW16.2 SW17.2 SW18.2 SW19.2 SW20.2 TP26.1(TP) U1.41(P20)
R4: CN3.13 TP7.1(TP) TP27.1(TP) U1.33(P13)
RFIO: L6.2 U1.3(RFIO)
SWDCLK: CN3.6 TP3.1(TP) U1.6(P1)
SWDIO: CN3.8 TP4.1(TP) U1.5(P2)
UART1_TX: CN3.14 TP11.1(TP) U1.56(P33)
USB_5V: C68.1 C77.1 D1.1 R66.1 R83.2 R84.1 R85.2 R90.2 TP14.1(TP) U9.A9(VBUS) U9.B4(VBUS) U12.1(VIN)
USB_DETEC: R66.2 R67.2 U1.11(P7)
VAUX: C5.1 DM17.1 R99.2 U1.28(VAUX)
VSTORE: C12.1 DM8.1 DM9.1 JP4.1 TP17.1(TP) U1.24(VSTORE)
XTALI_16M: U1.50(XTALI_16M) Y2.3(O/I)
XTALI_32K: U1.32(XTALI_32K) Y1.1
XTALO_16M: U1.51(XTALO_16M) Y2.1(I/O)
XTALO_32K: U1.31(XTALO_32K) Y1.2
N16434377: C19.1 R46.1 U1.21(HARV_OUT)
N16728527: C16.1 R1.1 R103.1 U1.22(VBAT)
N16728682: L3.2 U1.23(LEXT1)
N16790979: L3.1 U1.25(LEXT2)
N17106469: C51.2 DM11.2 IR1.2(ANODE)
N17106493: IR1.1(CATHODE) R26.2
N17106503: Q4.3(COLLECTOR) R26.1
N17106526: Q4.1(BASE) R27.2 R71.2
N17117313: C78.1 R90.1 U12.3(EN)
N17119841: R82.1 R87.2 U12.4(ADJ)
N17127838: C82.1 Q7.1(BASE) R84.2
N17128350: Q7.3(COLLECTOR) R85.1 R86.2 R88.2
N17165601: R87.1 R89.2
N17206240: DM12.2 R27.1
N17208011: C73.1 M1.5(VDD) R73.2
N17213943: DM13.2 R4.2
N17213945: DS1.2(ANODE) R4.1
N17247351: C21.2 C90.1 U3.1
N17247391: C29.1 C90.2 C93.1
N17247395: C24.1 C30.2 L5.1
N17247401: C31.2 L5.2 L6.1
N17247908: C38.2 R94.1 TP28.1(TP)
N17247928: C38.1 C43.1 L17.1
N17247938: C40.2 L16.1 R94.2
N17247944: C41.2 C46.1 L16.2 L19.1 L22.2
N17247979: C83.2 J10.1 L19.2
N17248015: C43.2 C47.1 L20.1
N17248063: C47.2 R95.1 TP29.1(TP)
N17248069: C46.2 L21.2 R95.2
N17248915: C71.1 DM3.1 U11.A2(VIN) U11.B1(EN) U11.D2(VSEL3)
N17248941: L23.1 U11.A1(SW)
N17248961: C72.1 DM4.1 L23.2 U11.C2(VOUT)
N17249135: Q5.3(DRAIN) R78.2
N17249147: Q5.1(GATE) Q6.3(COLLECTOR) R98.2
N17249185: Q6.1(BASE) R79.2 R80.2
N17251377: D2.1 DM15.1
N17253127: C84.1 C87.1 D3.1(A) DM9.2
N17253129: C85.1 C88.1 D3.2(K) DM10.2
N17253171: C86.1 D3.3(C)
N17271298: C24.2 U8.2(IN)
N17285732: BT1.1(POS) JP5.2
N17285738: C91.1 JP4.2
N17286004: C92.2 R105.1 R106.2
N17287499: C92.1 R104.1 S6.1
N17319709: DM16.2 DM17.2 DS2.2(ANODE)
N17319739: DS2.1(CATHODE) R77.1
N17319751: Q8.3(COLLECTOR) R77.2
N17319781: DM14.2 R109.1
N17319783: Q8.1(BASE) R109.2 R110.2
N17320465: D2.2 DM1.2
N17320939: DM1.1 R107.1
N17323537: C93.2 C94.1 U8.5(OUT)

Not connected (* = marked no-connect by the designer): CN3 5* 9*; U1 7(P3)* 8(P4)*; U9 21(GND)* 22(GND)* A4(VBUS)* A5(CC1)* A6(DP1)* A7(DN1)* A8(SBU1)* B5(CC2)* B6(DP2)* B7(DN2)* B8(SBU2)* B9(VBUS)*

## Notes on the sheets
sheet 1
- ATM2231_REMOTE_CONTROL_REF_DESIGN
- Release Date
- Revision
- Design Eng.
- Design Note
- 2024/03/11
- Rev. 01
- Albert
- Preliminary release
- Atmosic Technologies, Inc
- 910 E. Hamilton Ave, Suite 550
  Campbell, CA 95008, USA
- ATMOSIC TECHNOLOGIES INC
- Atmosic Technologies Proprietary and Confidential
sheet 2
- ATM2231_REMOTE_CONTROL_REF_DESIGN
- 2.4GHz
  PCB Antenna
- RFIO(BLE)
- RF
  Matching
- LED 2
  (2 GPIO)
- ATM2231
- CR2032
  Battery Holder
- VBAT
- (Internal VDDIO)
- IR LED
  (1 GPIO)
- D-MIC(PDM)
- 5x5
  Key Matrix
  (10 GPIO)
- VDDIO
- MP Request
- VDDIOP
- ATMOSIC TECHNOLOGIES INC
- 16MHz
  Crystal
- 32KHz
  Crystal
sheet 3
- BOOST
- IR LED
- ATM3231
- Default Internal VDDIO
- LED-R
- VDDIO OPTIONS
- 0.1uF change to NP
- 1000PF change to NP
- LED-G
- BUCK_2.5V
- RF
- 32K XTAL
- D-MIC
- KSO/KSI
- 16MHz XTAL
- KEY
- P1
- P2
- VOUT=2.5V
- P5
- P6
- P7
- P8
- P9
- P23
- P10
- P22
- P11
- P21
- P12
- P13
- P13
- P14
- P15
- P16
- P17
- P18
- P19
- Test Point
- TO INTERFACE BOARD
- P20
- P21
- P22
- PV CELL
- BATTERY ADC
- P23
- P24
- P25
- P26
- P28
- P29
- P30
- P31
- P32
- P33
- FLASH
- 7x7-QFN
- FPC TEST CONNECT
- Charger
- USB Plug-In Reset
- USB to LDO Charger
- Hybrid Supercap
- LPCOMP
- HW RESET
- VOUT=0.8V x((RA+RB)/RB)
  3.80V RA=18K, RB=4.8K
- RA=18Kohm
  RB=4.8Kohm
- ATMOSIC TECHNOLOGIES INC
sheet 4
- SW1
- SW2
- C_R
- C_R
- SW3
- POWER
  ON/OFF
- ??
- Column 0
- Column 1
- Column 2
- Column 3
- Column 4
- C_R
- P29
- P28
- P12
- P9
- P8
- SW4
- SW5
- ASSISTANT
- Row 0
- C_R
- C_R
- P23
- Profile Selector
- DSAHBOARD
- Row 1
- SW6
- P22
- C_R
- up
- Row 2
- SW7
- SW8
- SW7
- P21
- C_R
- C_R
- C_R
- Row 3
- left
- OK
- right
- SW10
- P20
- C_R
- Row 4
- down
- P13
- SW11
- SW12
- C_R
- C_R
- SW13
- BACK
- LIVE
- Key
- C_R
- HOME
- SW14
- SW17
- C_R
- C_R
- SW16
- volumn up
- CH+
- C_R
- SW15
- SW18
- Mute
- C_R
- C_R
- volume down
- CH-
- SW19
- SW20
- C_R
- C_R
- YOUTUBE
- NETFLEX
- SW21
- SW22
- ATMOSIC TECHNOLOGIES INC
- C_R
- C_R
- X
- X
sheet 5
- RFIO
- BOM need to change
- Differential
- Single End
- ATMOSIC TECHNOLOGIES INC
